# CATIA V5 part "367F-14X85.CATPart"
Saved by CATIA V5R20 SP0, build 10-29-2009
Part number: 367F-14X85
Definition: NONE
Nomenclature: 367F-14X85
Source: Unknown
Description: 367F-14X85
Bounding box of the stored display mesh (mm): x 0 to 85, y -14 to 14, z -14 to 14
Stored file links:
  C:\Users\Utente\Desktop\IO LAVORO\3D X SITO CF\X SITO\PLASTICA\3D files 367\367F-14X85.CATPart
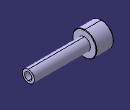
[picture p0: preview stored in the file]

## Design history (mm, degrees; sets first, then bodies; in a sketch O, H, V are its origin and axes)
Body1 "367F-14X85" (main body)
  Solid1: solid without history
